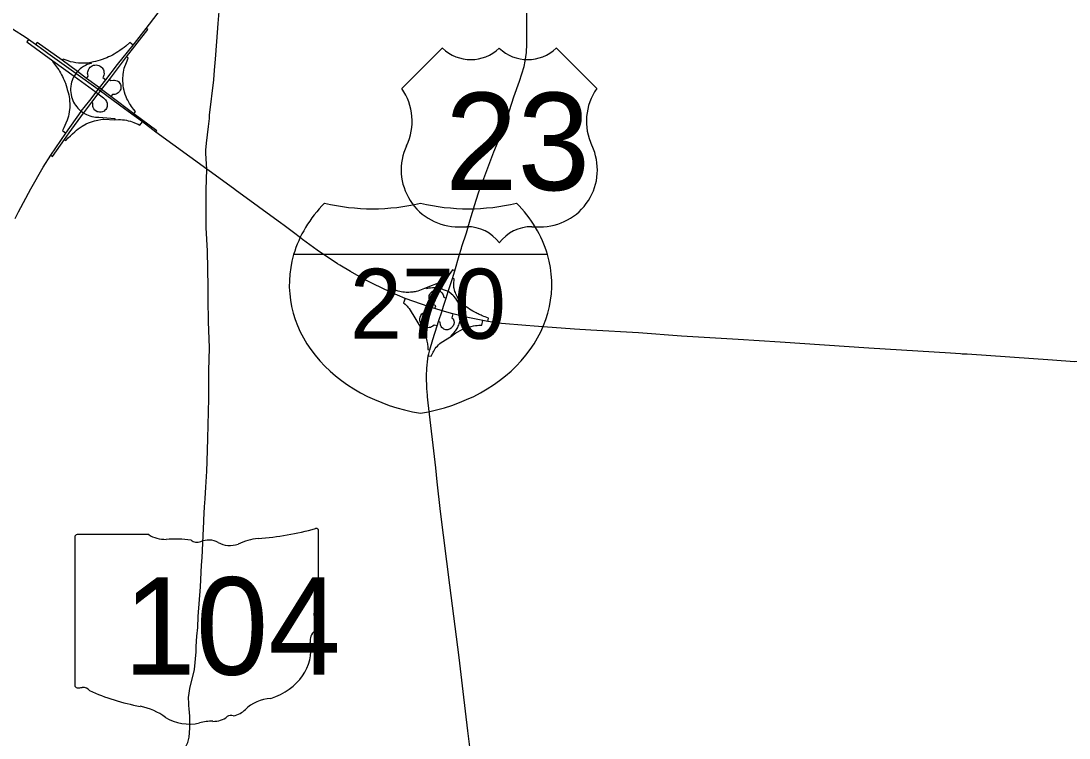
# Model space of a CAD drawing. Extents: x 0 to 34, y 0 to 22.
# Drawn here: x 5.072 to 6.458, y 15.124 to 16.072 of the extents above; entities that cross this region are included whole.
import ezdxf

# ---------------------------------------------------------------- set-up
doc = ezdxf.new("R2010")
doc.units = 0
for name, color, linetype in [('GM_X_Interchange_Ramps', 7, 'Continuous'), ('GM_X_Interstate_Route', 7, 'Continuous'), ('GM_X_Interstate_Shield', 7, 'Continuous'), ('GM_X_State_Route', 7, 'Continuous'), ('GM_X_State_Shield', 7, 'Continuous'), ('GM_X_US_Route', 7, 'Continuous'), ('GM_X_US_Shield', 7, 'Continuous')]:
    doc.layers.add(name, color=color, linetype=linetype)

msp = doc.modelspace()

# ---------------------------------------------------------------- linework, layer by layer
at = {"layer": 'GM_X_Interchange_Ramps'}
for points in [[(5.1116, 15.8944), (5.1141, 15.8928), (5.1298, 15.915), (5.1361, 15.9238), (5.1548, 15.9498), (5.1552, 15.9503), (5.166, 15.9644), (5.1745, 15.9754), (5.1772, 15.9789), (5.1789, 15.9811), (5.1892, 15.9946), (5.212, 16.0243), (5.2399, 16.0606), (5.238, 16.062)], [(5.0822, 16.0471), (5.08, 16.0441), (5.1144, 16.0191), (5.1426, 15.9987), (5.1668, 15.9812), (5.1715, 15.9776), (5.1745, 15.9754), (5.1813, 15.9702), (5.1839, 15.9677), (5.1853, 15.9655), (5.1861, 15.9633), (5.1864, 15.961), (5.1861, 15.9587), (5.1858, 15.9575), (5.1852, 15.9563), (5.1843, 15.9549), (5.1832, 15.9537), (5.1821, 15.9528), (5.1802, 15.9518), (5.1781, 15.9512), (5.176, 15.9512), (5.1742, 15.9515), (5.1729, 15.9519), (5.1712, 15.9529), (5.1698, 15.9541), (5.1686, 15.9557), (5.1678, 15.9573), (5.1673, 15.9588), (5.1672, 15.9603), (5.1673, 15.9633), (5.166, 15.9644)], [(5.2504, 15.9247), (5.2519, 15.9268), (5.2216, 15.9492), (5.1912, 15.972), (5.1789, 15.9811), (5.1759, 15.9834), (5.159, 15.9959), (5.147, 16.0049), (5.1268, 16.0198), (5.0935, 16.0434), (5.0915, 16.0406)], [(5.2204, 16.0398), (5.216, 16.0432), (5.2108, 16.0386), (5.2087, 16.0369), (5.2062, 16.035), (5.2031, 16.0327), (5.2002, 16.0308), (5.1981, 16.0295), (5.1957, 16.0281), (5.1931, 16.0267), (5.1905, 16.0254), (5.1882, 16.0242), (5.1857, 16.0231), (5.183, 16.022), (5.1797, 16.0208), (5.177, 16.0199), (5.1737, 16.0189), (5.1709, 16.0182), (5.1682, 16.0176), (5.1664, 16.0173), (5.1648, 16.0171), (5.1629, 16.0166), (5.1602, 16.0162), (5.1572, 16.016), (5.1546, 16.0159), (5.1518, 16.0159), (5.1483, 16.0161), (5.1446, 16.0166), (5.1412, 16.0172), (5.1377, 16.018), (5.1345, 16.019), (5.128, 16.0213), (5.1268, 16.0198)], [(5.1144, 16.0191), (5.1138, 16.0182), (5.1192, 16.0113), (5.1206, 16.0095), (5.1222, 16.0072), (5.1233, 16.0054), (5.1247, 16.0031), (5.126, 16.0007), (5.1274, 15.9982), (5.1282, 15.9964), (5.1294, 15.9937), (5.1303, 15.9915), (5.1311, 15.9894), (5.132, 15.9866), (5.1329, 15.9835), (5.1335, 15.9812), (5.1346, 15.9772), (5.1354, 15.9741), (5.1359, 15.9717), (5.1363, 15.9689), (5.1366, 15.9661), (5.1368, 15.9625), (5.1368, 15.9596), (5.1367, 15.9568), (5.1365, 15.9546), (5.136, 15.9516), (5.1355, 15.9486), (5.1349, 15.9462), (5.1341, 15.9433), (5.1332, 15.9407), (5.1316, 15.9368), (5.129, 15.9305), (5.127, 15.9269), (5.1317, 15.9235)], [(5.1648, 16.0171), (5.1651, 16.0157), (5.1629, 16.0151), (5.1599, 16.0142), (5.1574, 16.013), (5.1551, 16.0117), (5.1525, 16.0099), (5.1505, 16.0084), (5.1492, 16.0071), (5.1476, 16.0056), (5.147, 16.0049), (5.1463, 16.0041), (5.1449, 16.0023), (5.1446, 16.0019), (5.1431, 15.9996), (5.1426, 15.9987), (5.1419, 15.9975), (5.141, 15.9956), (5.14, 15.9932), (5.1393, 15.991), (5.1388, 15.9889), (5.1382, 15.9853), (5.1379, 15.9824), (5.1379, 15.9799), (5.1381, 15.9774), (5.1385, 15.9746), (5.1391, 15.9717), (5.1399, 15.9692), (5.1408, 15.9668), (5.1418, 15.9647), (5.143, 15.9625), (5.1444, 15.9603), (5.146, 15.9582), (5.1476, 15.9564), (5.1493, 15.9547), (5.1516, 15.9528), (5.152, 15.9525), (5.1535, 15.9514), (5.1552, 15.9503), (5.1562, 15.9497), (5.1587, 15.9484), (5.1609, 15.9474), (5.1633, 15.9465), (5.1661, 15.9457), (5.1686, 15.9451), (5.1709, 15.9448), (5.1733, 15.9446), (5.1754, 15.9445), (5.1965, 15.9431), (5.1965, 15.9413)], [(5.2216, 15.9492), (5.2238, 15.9522), (5.2211, 15.9552), (5.2197, 15.957), (5.2185, 15.9586), (5.2169, 15.961), (5.2157, 15.9628), (5.2147, 15.9645), (5.2134, 15.9671), (5.2124, 15.9691), (5.2113, 15.9716), (5.2102, 15.9745), (5.2093, 15.9776), (5.2087, 15.9798), (5.208, 15.9829), (5.2075, 15.9865), (5.2072, 15.9893), (5.207, 15.9922), (5.207, 15.9947), (5.2071, 15.9968), (5.2072, 15.9991), (5.2074, 16.001), (5.2078, 16.004), (5.2084, 16.0068), (5.2089, 16.0092), (5.2096, 16.0116), (5.2107, 16.0147), (5.2116, 16.0171), (5.2141, 16.0227), (5.212, 16.0243)], [(5.159, 15.9959), (5.1611, 15.9987), (5.1605, 16.0013), (5.1604, 16.0029), (5.1606, 16.0045), (5.1609, 16.0061), (5.1614, 16.0074), (5.1623, 16.009), (5.1637, 16.0106), (5.165, 16.0117), (5.1665, 16.0126), (5.168, 16.0132), (5.1698, 16.0136), (5.1717, 16.0137), (5.1735, 16.0135), (5.1753, 16.013), (5.1771, 16.012), (5.1786, 16.0109), (5.1797, 16.0097), (5.1806, 16.0085), (5.1812, 16.0072), (5.1817, 16.006), (5.182, 16.0041), (5.1821, 16.002), (5.1818, 16.0001), (5.1814, 15.9987), (5.1806, 15.9969), (5.1843, 15.9941)], [(5.1892, 15.9946), (5.191, 15.9932), (5.1944, 15.9937), (5.1958, 15.9937), (5.1978, 15.9933), (5.1995, 15.9926), (5.201, 15.9916), (5.2022, 15.9905), (5.2031, 15.9892), (5.2038, 15.9879), (5.2043, 15.9863), (5.2045, 15.9847), (5.2044, 15.9832), (5.2041, 15.9816), (5.2036, 15.9802), (5.2027, 15.9787), (5.2018, 15.9777), (5.2006, 15.9766), (5.1993, 15.9758), (5.1979, 15.9752), (5.1962, 15.9748), (5.1931, 15.9747), (5.1912, 15.972)], [(5.1298, 15.915), (5.1314, 15.914), (5.1346, 15.9172), (5.1377, 15.9202), (5.1405, 15.9228), (5.1433, 15.9253), (5.1459, 15.9275), (5.148, 15.9292), (5.1507, 15.9312), (5.1531, 15.9328), (5.1584, 15.9357), (5.1616, 15.9371), (5.1654, 15.9386), (5.1695, 15.9399), (5.1741, 15.9409), (5.1777, 15.9415), (5.1807, 15.9418), (5.182, 15.9419), (5.1965, 15.9413), (5.2011, 15.9414), (5.2037, 15.9414), (5.2064, 15.9413), (5.2091, 15.941), (5.2118, 15.9405), (5.2142, 15.94), (5.217, 15.9393), (5.2191, 15.9386), (5.2213, 15.9378), (5.2245, 15.9365), (5.2272, 15.9352), (5.2296, 15.9341), (5.2329, 15.9385)], [(5.6459, 15.7418), (5.6427, 15.7427), (5.6385, 15.7368), (5.6374, 15.7354), (5.6362, 15.734), (5.635, 15.7327), (5.6335, 15.7313), (5.6322, 15.7302), (5.6309, 15.7292), (5.6295, 15.7282), (5.628, 15.7272), (5.6259, 15.7261), (5.608, 15.719), (5.5969, 15.7149), (5.5948, 15.7143), (5.5932, 15.714), (5.5916, 15.7137), (5.5901, 15.7135), (5.5887, 15.7133), (5.5871, 15.7132), (5.5851, 15.7131), (5.583, 15.7131), (5.5813, 15.7131), (5.5792, 15.7133), (5.5771, 15.7135), (5.575, 15.7139), (5.5731, 15.7142), (5.5711, 15.7147), (5.5622, 15.7178), (5.5601, 15.7137)], [(5.6896, 15.6748), (5.6903, 15.6792), (5.686, 15.6807), (5.6841, 15.6814), (5.682, 15.6822), (5.6805, 15.6828), (5.6794, 15.6833), (5.6778, 15.684), (5.6766, 15.6846), (5.6753, 15.6852), (5.674, 15.6859), (5.6696, 15.6882), (5.665, 15.6911), (5.6629, 15.6925), (5.6606, 15.6942), (5.6589, 15.6956), (5.6573, 15.697), (5.6556, 15.6987), (5.6539, 15.7006), (5.653, 15.7016), (5.6518, 15.7032), (5.6508, 15.7045), (5.6502, 15.7054), (5.6487, 15.7078), (5.6471, 15.7114), (5.6465, 15.7129), (5.646, 15.7143), (5.6454, 15.7164), (5.6449, 15.7183), (5.6447, 15.7197), (5.6445, 15.7217), (5.6444, 15.7238), (5.6449, 15.7308), (5.6429, 15.7314)], [(5.6413, 15.6554), (5.6408, 15.6563), (5.6435, 15.6586), (5.6448, 15.6601), (5.6463, 15.6618), (5.6472, 15.6626), (5.648, 15.6639), (5.6488, 15.6653), (5.6497, 15.6669), (5.6504, 15.6684), (5.651, 15.67), (5.6516, 15.6716), (5.6532, 15.6769), (5.6539, 15.682), (5.6539, 15.6823), (5.6537, 15.6873), (5.6532, 15.692), (5.6514, 15.6966), (5.6502, 15.7), (5.6485, 15.7028), (5.647, 15.705), (5.6445, 15.7081), (5.6431, 15.7096), (5.6416, 15.7107), (5.638, 15.7138), (5.637, 15.7142), (5.6347, 15.7151), (5.6321, 15.7161), (5.6308, 15.7167), (5.6291, 15.7173), (5.6275, 15.7179), (5.6254, 15.7184), (5.6237, 15.7188), (5.6204, 15.7193), (5.6184, 15.7192), (5.6161, 15.719), (5.6138, 15.7188), (5.6118, 15.7186), (5.6085, 15.7179), (5.608, 15.719)], [(5.6193, 15.6916), (5.6206, 15.6955), (5.6178, 15.697), (5.6153, 15.6988), (5.6139, 15.7004), (5.6129, 15.7018), (5.6123, 15.7032), (5.6118, 15.7049), (5.6117, 15.7063), (5.6118, 15.7078), (5.6121, 15.7092), (5.6126, 15.7105), (5.6131, 15.7115), (5.6139, 15.7126), (5.6148, 15.7136), (5.6159, 15.7144), (5.6171, 15.7151), (5.6185, 15.7156), (5.62, 15.716), (5.6217, 15.7161), (5.6229, 15.7159), (5.6242, 15.7156), (5.6253, 15.7152), (5.6263, 15.7147), (5.6273, 15.714), (5.6282, 15.7131), (5.6289, 15.7123), (5.6295, 15.7114), (5.6304, 15.7097), (5.6313, 15.7067), (5.6344, 15.7056)], [(5.5802, 15.705), (5.5781, 15.6993), (5.5801, 15.6976), (5.5811, 15.6967), (5.582, 15.6958), (5.5829, 15.6949), (5.5839, 15.6937), (5.5854, 15.6916), (5.6043, 15.6604), (5.6052, 15.6588), (5.6058, 15.6573), (5.6066, 15.6556), (5.6072, 15.6542), (5.6078, 15.6526), (5.6083, 15.6509), (5.6089, 15.6488), (5.6093, 15.6469), (5.6096, 15.6452), (5.6098, 15.6438), (5.61, 15.6422), (5.61, 15.6378), (5.6127, 15.6373)], [(5.6223, 15.6688), (5.6186, 15.67), (5.6167, 15.6684), (5.6151, 15.6675), (5.6136, 15.6669), (5.6117, 15.6665), (5.6103, 15.6664), (5.6084, 15.6666), (5.6066, 15.6671), (5.605, 15.6679), (5.6036, 15.6688), (5.602, 15.6704), (5.601, 15.6719), (5.6, 15.6743), (5.5996, 15.6764), (5.5996, 15.6783), (5.5999, 15.6802), (5.6009, 15.6825), (5.6023, 15.6846), (5.6043, 15.6863), (5.6062, 15.6874), (5.6079, 15.6879), (5.6101, 15.6882), (5.6119, 15.6939)], [(5.6432, 15.6849), (5.642, 15.6795), (5.6436, 15.678), (5.6447, 15.6755), (5.6448, 15.6734), (5.6445, 15.671), (5.6437, 15.6691), (5.6424, 15.6675), (5.6417, 15.6665), (5.6408, 15.6657), (5.6398, 15.665), (5.6387, 15.6644), (5.6376, 15.664), (5.6364, 15.6638), (5.6352, 15.6637), (5.6341, 15.6638), (5.6326, 15.6641), (5.6315, 15.6646), (5.6304, 15.6652), (5.6293, 15.6661), (5.6287, 15.6668), (5.6279, 15.6679), (5.6273, 15.6691), (5.6269, 15.6704), (5.6263, 15.6739), (5.6242, 15.6745)], [(5.6107, 15.6294), (5.6146, 15.6287), (5.6171, 15.634), (5.618, 15.6356), (5.6191, 15.6374), (5.62, 15.6388), (5.6212, 15.6405), (5.6227, 15.6422), (5.6244, 15.644), (5.6258, 15.6454), (5.6277, 15.6469), (5.6413, 15.6554), (5.6472, 15.6598), (5.6554, 15.6641), (5.6576, 15.6651), (5.6593, 15.6657), (5.6612, 15.6664), (5.663, 15.667), (5.6653, 15.6677), (5.6676, 15.6682), (5.6704, 15.6688), (5.673, 15.6692), (5.6755, 15.6695), (5.6776, 15.6697), (5.6817, 15.6698), (5.6827, 15.676)]]:
    msp.add_lwpolyline(points, dxfattribs=at)
at = {"layer": 'GM_X_Interstate_Route'}
for points in [[(5.2423, 16.0677), (5.2709, 16.1053)], [(5.0822, 16.0471), (5.0791, 16.0493), (5.0611, 16.0611), (5.0476, 16.0692)], [(5.2222, 16.042), (5.238, 16.062)], [(5.238, 16.062), (5.2422, 16.0676), (5.2423, 16.0677)], [(5.0915, 16.0406), (5.0822, 16.0471)], [(5.1742, 15.9811), (5.1449, 16.0023), (5.1448, 16.0025), (5.1078, 16.0288), (5.1023, 16.0328), (5.0915, 16.0406)], [(5.1742, 15.9811), (5.1759, 15.9834), (5.1843, 15.9941), (5.1998, 16.0141), (5.2204, 16.0398), (5.2222, 16.042)], [(5.1317, 15.9235), (5.1519, 15.9523), (5.152, 15.9525), (5.1632, 15.9665), (5.1715, 15.9776), (5.1742, 15.9811)], [(5.2093, 15.9555), (5.1772, 15.9789), (5.1742, 15.9811)], [(5.3241, 15.8715), (5.3182, 15.8758), (5.2504, 15.9247), (5.2329, 15.9385), (5.2139, 15.9522), (5.2093, 15.9555)], [(5.1116, 15.8944), (5.1317, 15.9235)], [(5.0646, 15.8106), (5.0692, 15.8195), (5.0852, 15.85), (5.1016, 15.8784), (5.1116, 15.8944)], [(5.3556, 15.8486), (5.3548, 15.8491), (5.3241, 15.8715)], [(5.4184, 15.8027), (5.4173, 15.8035), (5.3556, 15.8486)], [(5.4437, 15.7838), (5.4309, 15.7935), (5.4184, 15.8027)], [(5.4936, 15.749), (5.4908, 15.7507), (5.464, 15.769), (5.4445, 15.7831), (5.4437, 15.7838)], [(5.5802, 15.705), (5.5601, 15.7137), (5.5386, 15.7241), (5.5255, 15.7307), (5.508, 15.7405), (5.4936, 15.749)], [(5.6144, 15.6931), (5.6119, 15.6939), (5.5802, 15.705)], [(5.6289, 15.6888), (5.6193, 15.6916), (5.6144, 15.6931)], [(5.6585, 15.6809), (5.6551, 15.6816), (5.6539, 15.682), (5.6432, 15.6849), (5.6289, 15.6888)], [(6.3142, 15.6318), (6.3012, 15.6329), (6.1931, 15.6393), (6.0759, 15.6473), (6.0203, 15.6507), (5.9455, 15.6554), (5.8885, 15.6595), (5.8256, 15.6632), (5.8042, 15.6645), (5.7509, 15.6685), (5.7395, 15.6694), (5.7076, 15.6718), (5.6896, 15.6748), (5.6827, 15.676), (5.6585, 15.6809)], [(6.5413, 15.6307), (6.5297, 15.6277), (6.5167, 15.625), (6.4976, 15.6224), (6.4868, 15.6217), (6.4651, 15.6214), (6.4359, 15.6236), (6.3233, 15.6313), (6.3166, 15.6316), (6.3142, 15.6318)]]:
    msp.add_lwpolyline(points, dxfattribs=at)
at = {"layer": 'GM_X_Interstate_Shield'}
msp.add_line((5.7683, 15.7632), (5.4327, 15.7632), dxfattribs=at)
msp.add_line((5.7683, 15.7632), (5.4327, 15.7632), dxfattribs=at)
for centre, start_param, end_param in [((5.6439, 15.7235), 2.47259, 2.911027), ((5.5371, 15.9971), 4.415841, 5.008937), ((5.6639, 15.9971), 4.415841, 5.008937), ((5.5571, 15.7235), 0.230566, 0.669003), ((5.6439, 15.7235), 2.911027, 4.511031), ((5.5571, 15.7235), 4.913747, 6.513751)]:
    msp.add_ellipse(centre, major_axis=(0.2169, 0), ratio=0.8, start_param=start_param, end_param=end_param, dxfattribs=at)
at = {"layer": 'GM_X_State_Route'}
for points in [[(5.3217, 15.9471), (5.3271, 15.9938), (5.328, 16.0067), (5.3294, 16.0212), (5.331, 16.0445), (5.3331, 16.0684), (5.3347, 16.0898), (5.3347, 16.0898)], [(5.3173, 15.8239), (5.3173, 15.8479), (5.3173, 15.8485), (5.3182, 15.8758), (5.3167, 15.8965), (5.3168, 15.9012), (5.3176, 15.9103), (5.32, 15.9324), (5.3213, 15.943), (5.3215, 15.9459), (5.3216, 15.9466), (5.3217, 15.9471)], [(5.3197, 15.7049), (5.3196, 15.7073), (5.3198, 15.7202), (5.3189, 15.7678), (5.3173, 15.7983), (5.3173, 15.8224), (5.3173, 15.8229), (5.3173, 15.8239)], [(5.3184, 15.4894), (5.3195, 15.5202), (5.3205, 15.5727), (5.3207, 15.6093), (5.3215, 15.6398), (5.32, 15.6745), (5.3198, 15.7038), (5.3197, 15.7049)], [(5.3135, 15.3988), (5.3142, 15.4127), (5.3151, 15.4296), (5.3158, 15.4403), (5.3158, 15.4409), (5.3167, 15.4559), (5.318, 15.4767), (5.3184, 15.4894)], [(5.3131, 15.3914), (5.3133, 15.3942), (5.3135, 15.3988)], [(5.3094, 15.3238), (5.3095, 15.324), (5.3111, 15.3527), (5.3116, 15.3629), (5.3131, 15.3914)], [(5.2949, 15.1595), (5.2948, 15.1607), (5.2939, 15.1784), (5.2941, 15.1806), (5.2957, 15.1898), (5.3016, 15.2146), (5.3039, 15.2381), (5.304, 15.2452), (5.3049, 15.2586), (5.3063, 15.2702), (5.3067, 15.2847), (5.3094, 15.3238)], [(5.2669, 15.0743), (5.2673, 15.0755), (5.2687, 15.0786), (5.2726, 15.0851), (5.2761, 15.0899), (5.2796, 15.0952), (5.2855, 15.1033), (5.2886, 15.1093), (5.2929, 15.1182), (5.2948, 15.1255), (5.2956, 15.137), (5.2954, 15.1512), (5.2949, 15.1595)]]:
    msp.add_lwpolyline(points, dxfattribs=at)
at = {"layer": 'GM_X_State_Shield'}
for p, q in [((5.2411, 15.393), (5.1468, 15.393)), ((5.4657, 15.2955), (5.4657, 15.3978)), ((5.1436, 15.3896), (5.1436, 15.194)), ((5.4657, 15.2956), (5.4657, 15.2955))]:
    msp.add_line(p, q, dxfattribs=at)
for centre, major_axis, start_param, end_param in [((5.1473, 15.39), (0.00373, 0), 1.712693, 3.28349), ((5.2636, 15.4157), (0.0362, 0), 4.042523, 4.731795), ((5.351, 15.6596), (0.3416, 0), 4.814394, 5.042369), ((5.4622, 15.3983), (0.00359, 0), 6.141152, 7.989035), ((5.2756, 15.2832), (0.1299, 0), 1.404758, 1.657858), ((5.3051, 15.3911), (0.0104, 0), 3.836095, 5.185415), ((5.3204, 15.3685), (0.0217, 0), 0.950623, 2.079405), ((5.3484, 15.3995), (0.0261, 0), 4.081561, 5.145723), ((5.3946, 15.3333), (0.0687, 0), 1.699011, 2.107814), ((5.4649, 15.288), (0.00555, 0), 1.883978, 3.671073), ((5.4296, 15.2751), (0.0333, 0), 5.934695, 6.695948), ((5.4619, 15.2951), (0.00384, 0), 5.05454, 6.418171), ((5.4786, 15.2527), (0.0242, 0), 2.387724, 3.262537), ((5.3701, 15.2397), (0.0854, 0), 5.101752, 6.440018), ((5.1473, 15.1936), (0.00376, 0), 3.00124, 4.508301), ((5.1479, 15.2136), (0.0287, 0), 4.665946, 4.897461), ((5.1538, 15.1828), (0.0104, 0), 0.519207, 1.627899), ((5.2846, 15.3585), (0.2467, 0), 4.195997, 4.488961), ((5.4062, 15.1391), (0.0468, 0), 1.647645, 2.488434), ((5.211, 15.1062), (0.0772, 0), 0.823519, 1.323587), ((5.3469, 15.1751), (0.0276, 0), 4.937069, 5.64225), ((5.2945, 15.1818), (0.049, 0), 4.026481, 4.996735), ((5.3228, 15.1142), (0.0402, 0), 1.495662, 1.94098), ((5.3264, 15.1671), (0.0261, 0), 4.691044, 5.507374), ((5.35, 15.1482), (0.00735, 0), 1.147584, 2.315152)]:
    msp.add_ellipse(centre, major_axis=major_axis, ratio=0.8, start_param=start_param, end_param=end_param, dxfattribs=at)
at = {"layer": 'GM_X_US_Route'}
for points in [[(5.7239, 15.9714), (5.7312, 15.9924), (5.7375, 16.0118), (5.739, 16.0188), (5.7399, 16.0243), (5.7405, 16.0302), (5.7408, 16.041), (5.7406, 16.1307), (5.7407, 16.147), (5.7407, 16.1616), (5.7408, 16.1776), (5.7408, 16.1958), (5.7407, 16.2106), (5.7407, 16.2141), (5.7408, 16.2218), (5.741, 16.2362), (5.7413, 16.2625), (5.7412, 16.2676), (5.7414, 16.2954), (5.7414, 16.3104), (5.7414, 16.3263), (5.7416, 16.3522), (5.7416, 16.3565)], [(5.7081, 15.9262), (5.7144, 15.9437), (5.7179, 15.9534), (5.7239, 15.9714)], [(5.703, 15.9127), (5.7069, 15.9228), (5.7081, 15.9262)], [(5.6935, 15.8881), (5.6976, 15.8988), (5.703, 15.9127)], [(5.6676, 15.8134), (5.6676, 15.8134), (5.6742, 15.835), (5.6775, 15.8462), (5.6935, 15.8881)], [(5.6546, 15.7717), (5.6553, 15.7738), (5.6611, 15.792), (5.6662, 15.8089), (5.6676, 15.8134)], [(5.631, 15.6951), (5.6344, 15.7056), (5.637, 15.7142), (5.6429, 15.7314), (5.6459, 15.7418), (5.6514, 15.7617), (5.6546, 15.7717)], [(5.6096, 15.5774), (5.6087, 15.5859), (5.6082, 15.6022), (5.6087, 15.6131), (5.6102, 15.6255), (5.6107, 15.6294), (5.6113, 15.6318), (5.6127, 15.6373), (5.6167, 15.6507), (5.6223, 15.6688), (5.6242, 15.6745), (5.6289, 15.6888)], [(5.6289, 15.6888), (5.631, 15.6951)], [(5.6099, 15.575), (5.6096, 15.5774)], [(5.6735, 14.9989), (5.6736, 14.9995), (5.6744, 15.0107), (5.6748, 15.025), (5.6745, 15.0342), (5.6741, 15.0416), (5.673, 15.0597), (5.6673, 15.0983), (5.6628, 15.1338), (5.6567, 15.1857), (5.6515, 15.2308), (5.6393, 15.326), (5.6269, 15.4235), (5.6226, 15.4628), (5.6205, 15.4811), (5.6107, 15.5672), (5.6099, 15.575)]]:
    msp.add_lwpolyline(points, dxfattribs=at)
at = {"layer": 'GM_X_US_Shield'}
for p, q in [((5.6295, 16.0361), (5.5758, 15.9824)), ((5.8335, 15.9824), (5.7798, 16.0361)), ((5.6509, 15.7999), (5.6617, 15.7999)), ((5.7476, 15.7999), (5.7583, 15.7999))]:
    msp.add_line(p, q, dxfattribs=at)
for centre, radius, start, end in [((5.667, 16.0744), 0.0537, 225.573, 314.427), ((5.7422, 16.0744), 0.0537, 225.573, 314.427), ((5.5142, 15.9393), 0.0752, 334.5471, 35.0009), ((5.895, 15.9393), 0.0752, 144.9991, 205.4529), ((5.6501, 15.875), 0.0752, 154.8319, 270.6383), ((5.7591, 15.875), 0.0752, 269.3617, 25.1681), ((5.6617, 15.7462), 0.0537, 36.8699, 90), ((5.7476, 15.7462), 0.0537, 90, 143.1301)]:
    msp.add_arc(centre, radius, start, end, dxfattribs=at)

# ---------------------------------------------------------------- texts
at = {"layer": 'GM_X_Interstate_Shield'}
msp.add_text('270', height=0.09255, dxfattribs=at).set_placement((5.507, 15.6518))
at = {"layer": 'GM_X_State_Shield'}
msp.add_text('104', height=0.12885, dxfattribs=at).set_placement((5.2076, 15.2078))
at = {"layer": 'GM_X_US_Shield'}
msp.add_text('23', height=0.12885, dxfattribs=at).set_placement((5.6329, 15.8482))

doc.saveas('drawing.dxf')
